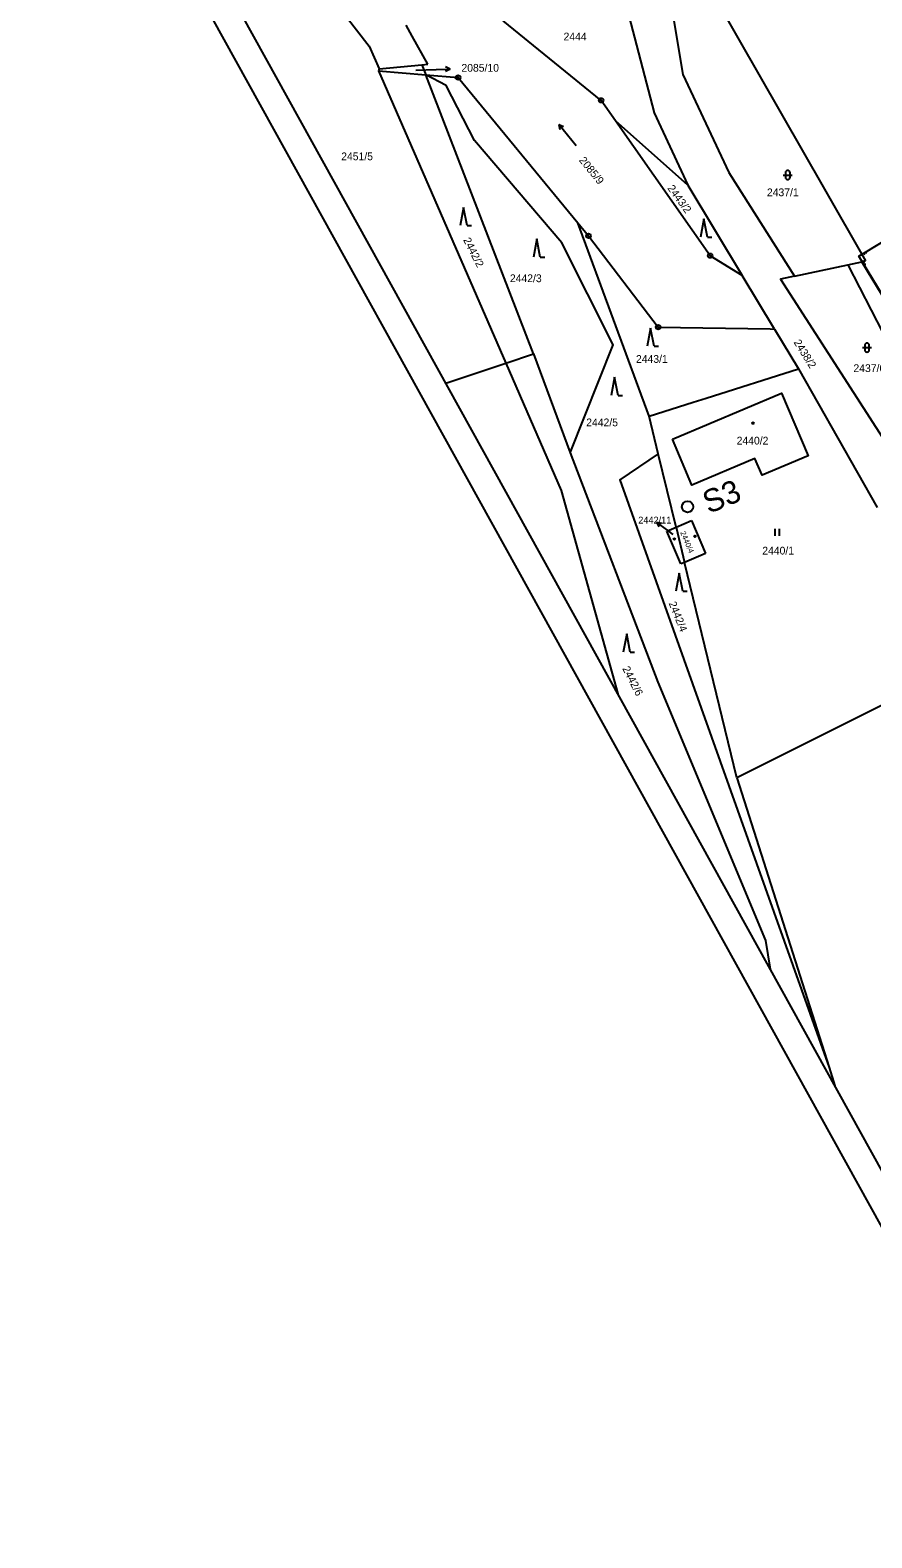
# Model space of a CAD drawing. Extents: x -483721 to -481876, y -1129170 to -1127366.
# Drawn here: x -482654.9 to -482470.6, y -1128454.5 to -1128124.2 of the extents above; entities that cross this region are included whole.
import ezdxf

# ---------------------------------------------------------------- set-up
doc = ezdxf.new("R2010")
doc.units = 0
for name, color, linetype in [('Hranice parcel', 7, 'Continuous'), ('Parcelní čísla', 7, 'Continuous'), ('Pop  PČ popisy', 7, 'Continuous'), ('U_IGP', 7, 'Continuous'), ('Značky bodu BP', 7, 'Continuous'), ('Značky budov', 7, 'Continuous'), ('Značky kultur', 7, 'Continuous'), ('ˇ8', 7, 'Continuous')]:
    doc.layers.add(name, color=color, linetype=linetype)

msp = doc.modelspace()

# ---------------------------------------------------------------- linework, layer by layer
for p, q in [((-482430.72, -1128454.53), (-482654.9, -1128049.38)), ((-482428.38, -1128446.38), (-482646.74, -1128051.72))]:
    msp.add_line(p, q)
at = {"layer": 'Hranice parcel'}
for p, q in [((-482578.47, -1128132.71), (-482578.57, -1128133.15)), ((-482578.57, -1128133.15), (-482550.74, -1128197.15)), ((-482578.57, -1128133.15), (-482568.26, -1128134)), ((-482578.47, -1128132.71), (-482569.11, -1128131.8)), ((-482569.11, -1128131.8), (-482567.8, -1128131.67)), ((-482569.11, -1128131.8), (-482568.26, -1128134)), ((-482544.63, -1128195.09), (-482568.26, -1128134)), ((-482568.26, -1128134), (-482561.18, -1128134.58)), ((-482561.18, -1128134.58), (-482534.96, -1128166.41)), ((-482510.84, -1128158.2), (-482526.72, -1128144.04)), ((-482510.84, -1128158.2), (-482498.95, -1128177.95)), ((-482519.33, -1128208.78), (-482534.96, -1128166.41)), ((-482487.52, -1128178.13), (-482475.8, -1128175.59)), ((-482475.8, -1128175.59), (-482472.77, -1128174.94)), ((-482475.8, -1128175.59), (-482443.21, -1128239.32)), ((-482471.94, -1128174.76), (-482472.77, -1128174.94)), ((-482491.88, -1128189.7), (-482498.95, -1128177.95)), ((-482491.88, -1128189.7), (-482486.64, -1128198.4)), ((-482563.84, -1128201.56), (-482550.74, -1128197.15)), ((-482550.74, -1128197.15), (-482544.63, -1128195.09)), ((-482544.63, -1128195.09), (-482536.63, -1128216.83)), ((-482486.64, -1128198.4), (-482469.4, -1128228.8)), ((-482517.32, -1128217.05), (-482519.33, -1128208.78)), ((-482513.43, -1128233.07), (-482517.32, -1128217.05)), ((-482515.46, -1128233.95), (-482513.43, -1128233.07)), ((-482513.43, -1128233.07), (-482510.04, -1128231.61)), ((-482513.43, -1128233.07), (-482511.55, -1128240.81)), ((-482510.04, -1128231.61), (-482506.97, -1128238.88)), ((-482512.37, -1128241.16), (-482515.46, -1128233.95)), ((-482506.97, -1128238.88), (-482511.55, -1128240.81)), ((-482511.55, -1128240.81), (-482512.37, -1128241.16)), ((-482500.1, -1128287.99), (-482511.55, -1128240.81)), ((-482466.51, -1128271.25), (-482500.1, -1128287.99)), ((-482500.1, -1128287.99), (-482479.93, -1128351.49)), ((-482479.93, -1128351.49), (-482478.65, -1128355.53))]:
    msp.add_line(p, q, dxfattribs=at)
for points in [[(-482518.86, -1128092.67), (-482480.93, -1128159.02), (-482471.94, -1128174.76)], [(-482518.86, -1128092.67), (-482517.97, -1128098), (-482511.94, -1128133.9), (-482501.85, -1128155.36), (-482487.52, -1128178.13)], [(-482617, -1128104.43), (-482593.47, -1128111.08), (-482580.68, -1128127.71), (-482578.47, -1128132.71)], [(-482524.19, -1128119.36), (-482518.25, -1128142.32), (-482510.84, -1128158.2)], [(-482567.8, -1128131.67), (-482571.2, -1128125.5), (-482572.52, -1128123.09)], [(-482526.72, -1128144.04), (-482529.84, -1128139.59), (-482551.29, -1128122.13)], [(-482536.63, -1128216.83), (-482527.18, -1128193.18), (-482538.45, -1128170.78), (-482557.56, -1128148.38), (-482563.79, -1128136.36), (-482568.26, -1128134)], [(-482498.95, -1128177.95), (-482505.97, -1128173.62), (-482526.72, -1128144.04)], [(-482534.96, -1128166.41), (-482532.6, -1128169.27), (-482517.34, -1128189.27), (-482492.79, -1128189.68), (-482491.88, -1128189.7)], [(-482378.58, -1128267.55), (-482422.4, -1128234.54), (-482424.97, -1128232.6), (-482436.98, -1128222.89), (-482441.06, -1128219.38), (-482451.1, -1128211.21), (-482453.27, -1128206.98), (-482457.35, -1128200.28), (-482472.77, -1128174.94)], [(-482487.52, -1128178.13), (-482490.56, -1128178.78), (-482466.89, -1128215.52), (-482461.75, -1128222.56), (-482459.4, -1128226.34), (-482451.11, -1128233.8), (-482446.93, -1128236.88)], [(-482550.74, -1128197.15), (-482538.58, -1128225.1), (-482526.2, -1128269.59)], [(-482519.33, -1128208.78), (-482509.7, -1128205.72), (-482506.84, -1128204.81), (-482486.64, -1128198.4)], [(-482514.21, -1128213.81), (-482490.31, -1128203.73), (-482484.51, -1128217.49), (-482494.6, -1128221.74), (-482496.15, -1128218.09), (-482509.96, -1128223.89), (-482514.21, -1128213.81)], [(-482536.63, -1128216.83), (-482517.39, -1128267.06), (-482493.81, -1128323.66), (-482492.8, -1128329.96)], [(-482517.32, -1128217.05), (-482525.78, -1128222.75), (-482479.93, -1128351.49)]]:
    msp.add_lwpolyline(points, dxfattribs=at)
at = {"layer": 'Pop  PČ popisy'}
for p, q in [((-482570.42, -1128132.97), (-482565.94, -1128132.84)), ((-482565.94, -1128132.84), (-482562.94, -1128132.74)), ((-482562.94, -1128132.74), (-482563.96, -1128132.27)), ((-482562.94, -1128132.74), (-482563.92, -1128133.27)), ((-482515.3, -1128233.78), (-482517.73, -1128232.02)), ((-482517.73, -1128232.02), (-482516.62, -1128232.2)), ((-482517.73, -1128232.02), (-482517.21, -1128233.01)), ((-482514.07, -1128234.68), (-482515.3, -1128233.78))]:
    msp.add_line(p, q, dxfattribs=at)
at = {"layer": 'U_IGP'}
msp.add_circle((-482510.92, -1128228.63), 1.22, dxfattribs=at)
at = {"layer": 'Značky bodu BP'}
for centre, radius in [((-482561.18, -1128134.58), 0.5), ((-482561.18, -1128134.58), 0.0303), ((-482529.84, -1128139.59), 0.5), ((-482529.84, -1128139.59), 0.0303), ((-482532.6, -1128169.27), 0.5), ((-482532.6, -1128169.27), 0.0303), ((-482505.97, -1128173.62), 0.5), ((-482505.97, -1128173.62), 0.0303), ((-482517.34, -1128189.27), 0.5), ((-482517.34, -1128189.27), 0.0303)]:
    msp.add_circle(centre, radius, dxfattribs=at)
at = {"layer": 'Značky budov'}
for centre in [(-482496.57, -1128210.3), (-482513.81, -1128235.7), (-482509.29, -1128235.13)]:
    msp.add_circle(centre, 0.175, dxfattribs=at)
at = {"layer": 'Značky kultur'}
for p, q in [((-482535.31, -1128149.53), (-482539.08, -1128144.87)), ((-482539.08, -1128144.87), (-482538.86, -1128145.95)), ((-482539.08, -1128144.87), (-482538.08, -1128145.31)), ((-482489.97, -1128155.95), (-482487.97, -1128155.95)), ((-482489.47, -1128155.45), (-482489.47, -1128156.45)), ((-482488.47, -1128156.45), (-482488.47, -1128155.45)), ((-482559.97, -1128163.03), (-482560.72, -1128167.03)), ((-482559.22, -1128167.03), (-482559.97, -1128163.03)), ((-482559.22, -1128167.03), (-482558.22, -1128167.03)), ((-482507.32, -1128165.58), (-482508.07, -1128169.58)), ((-482506.57, -1128169.58), (-482507.32, -1128165.58)), ((-482543.92, -1128169.93), (-482544.67, -1128173.93)), ((-482543.17, -1128173.93), (-482543.92, -1128169.93)), ((-482506.57, -1128169.58), (-482505.57, -1128169.58)), ((-482543.17, -1128173.93), (-482542.17, -1128173.93)), ((-482519.01, -1128189.47), (-482519.76, -1128193.47)), ((-482518.26, -1128193.47), (-482519.01, -1128189.47)), ((-482518.26, -1128193.47), (-482517.26, -1128193.47)), ((-482472.61, -1128193.75), (-482470.61, -1128193.75)), ((-482472.11, -1128193.25), (-482472.11, -1128194.25)), ((-482471.11, -1128194.25), (-482471.11, -1128193.25)), ((-482526.88, -1128200.26), (-482527.63, -1128204.26)), ((-482526.13, -1128204.26), (-482526.88, -1128200.26)), ((-482526.13, -1128204.26), (-482525.13, -1128204.26)), ((-482491.76, -1128235), (-482491.76, -1128233.5)), ((-482490.76, -1128235), (-482490.76, -1128233.5)), ((-482512.73, -1128243.15), (-482513.48, -1128247.15)), ((-482511.98, -1128247.15), (-482512.73, -1128243.15)), ((-482511.98, -1128247.15), (-482510.98, -1128247.15)), ((-482524.25, -1128256.5), (-482525, -1128260.5)), ((-482523.5, -1128260.5), (-482524.25, -1128256.5)), ((-482523.5, -1128260.5), (-482522.5, -1128260.5))]:
    msp.add_line(p, q, dxfattribs=at)
for centre, start, end in [((-482488.97, -1128155.45), 0, 180), ((-482488.97, -1128156.45), 180, 359.9879), ((-482471.61, -1128193.25), 0, 180), ((-482471.61, -1128194.25), 180, 359.9879)]:
    msp.add_arc(centre, 0.5, start, end, dxfattribs=at)
at = {"layer": 'ˇ8'}
for p, q in [((-482472.14, -1128172.93), (-482472.3, -1128173.4)), ((-482471.67, -1128173.09), (-482472.14, -1128172.93)), ((-482472.3, -1128174.91), (-482472.38, -1128175.4)), ((-482472.38, -1128175.4), (-482471.9, -1128175.48))]:
    msp.add_line(p, q, dxfattribs=at)
msp.add_lwpolyline([(-482433.73, -1128225.42), (-482441.02, -1128219.33), (-482451.04, -1128211.16), (-482453.21, -1128206.95), (-482457.29, -1128200.24), (-482473.4, -1128173.72), (-482468.04, -1128170.5), (-482462.04, -1128177.46)], dxfattribs=at)

# ---------------------------------------------------------------- texts
at = {"layer": 'Parcelní čísla'}
for s, height, p in [('2444', 1.7, (-482538.07, -1128126.45)), ('2085/10', 1.7, (-482560.44, -1128133.31)), ('2451/5', 1.7, (-482586.77, -1128152.71)), ('2437/1', 1.7, (-482493.53, -1128160.59)), ('2442/3', 1.7, (-482549.82, -1128179.42)), ('2443/1', 1.7, (-482522.21, -1128197.1)), ('2437/6', 1.7, (-482474.58, -1128199.11)), ('2442/5', 1.7, (-482533.11, -1128211)), ('2440/2', 1.7, (-482500.16, -1128214.99)), ('2442/11', 1.5, (-482521.72, -1128232.31)), ('2440/1', 1.7, (-482494.55, -1128239.09))]:
    msp.add_text(s, height=height, dxfattribs=at).set_placement(p)
for s, height, rotation, p in [('2085/9', 1.7, 309, (-482534.77, -1128152.77)), ('2443/2', 1.7, 306, (-482515.4, -1128158.87)), ('2442/2', 1.7, 297, (-482560.1, -1128170.16)), ('2438/2', 1.7, 302, (-482487.74, -1128192.61)), ('2440/4', 1.2, 293, (-482512.55, -1128234.26)), ('2442/4', 1.7, 292, (-482515.08, -1128249.77)), ('2442/6', 1.7, 297, (-482525.25, -1128264.07))]:
    msp.add_text(s, height=height, rotation=rotation, dxfattribs=at).set_placement(p)
at = {"layer": 'U_IGP'}
msp.add_text('S3', height=5, rotation=22.5289, dxfattribs=at).set_placement((-482506.29, -1128230.23))

doc.saveas('drawing.dxf')
